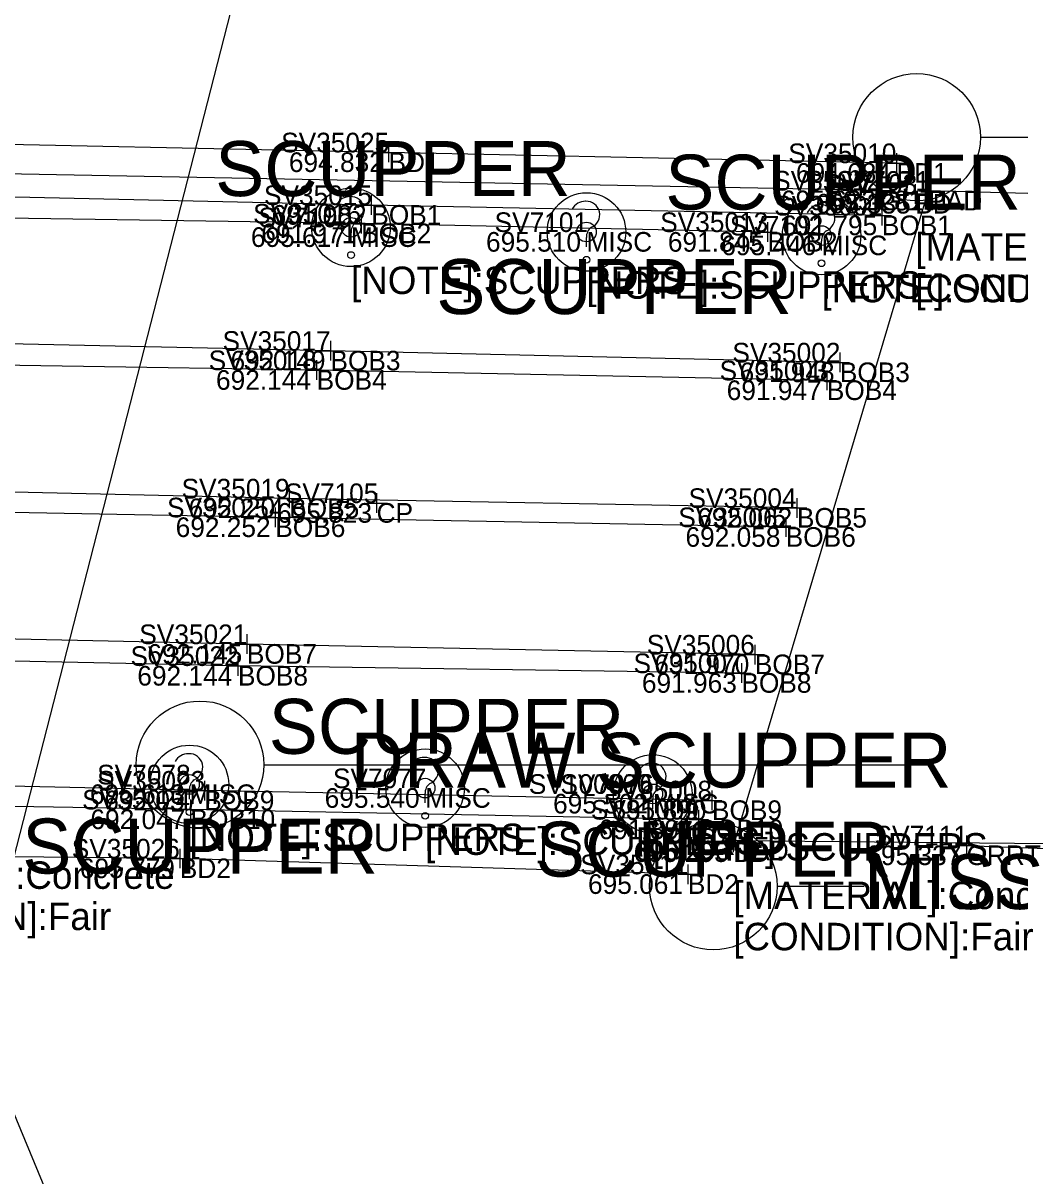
# Model space of a CAD drawing. Extents: x 1660019 to 1662995, y 619975 to 620342.
# Drawn here: x 1661479.7 to 1661530.4, y 620194.9 to 620253.7 of the extents above; entities that cross this region are included whole.
import ezdxf

# ---------------------------------------------------------------- set-up
doc = ezdxf.new("R2010")
doc.units = 0
for name, color, linetype in [('BR_X_Rail_Object', 7, 'Continuous'), ('BR_X_SV_Bottom_of_Beam', 7, 'Continuous'), ('BR_X_SV_Bottom_of_Beam_Text', 7, 'Continuous'), ('BR_X_SV_Deck_Top', 7, 'Continuous'), ('BR_X_SV_Deck_Top_Text', 7, 'Continuous'), ('PV_X_Curb', 7, 'Continuous'), ('RD_P_GR_Lt', 7, 'Continuous'), ('RD_X_Concrete_Pad', 7, 'Continuous'), ('RD_X_GR_Bar', 7, 'Continuous'), ('RD_X_GR_Rt', 7, 'Continuous'), ('RD_X_Misc_Items', 7, 'Continuous'), ('RD_X_Text', 7, 'Continuous'), ('RD_X_Wall', 7, 'Continuous'), ('SC_Scratch6', 7, 'Continuous'), ('SV_X_Text', 7, 'Continuous'), ('SV_X_Toe_of_Slope', 7, 'Continuous')]:
    doc.layers.add(name, color=color, linetype=linetype)

msp = doc.modelspace()

# ---------------------------------------------------------------- linework, layer by layer
at = {"layer": 'BR_X_SV_Bottom_of_Beam'}
for points in [[(1661523.404, 620243.849), (1661497.415, 620244.383), (1661471.694, 620244.95), (1661445.773, 620245.45), (1661419.903, 620245.974), (1661394.009, 620246.51), (1661368.147, 620247.032), (1661342.287, 620247.488), (1661316.311, 620248.045), (1661290.557, 620248.602), (1661264.648, 620249.031), (1661238.6, 620249.579)], [(1661517.582, 620243.008), (1661496.897, 620243.44), (1661470.919, 620243.838), (1661445.09, 620244.441), (1661419.147, 620244.946), (1661393.26, 620245.417), (1661367.358, 620245.921), (1661341.629, 620246.518), (1661315.646, 620247.115), (1661289.746, 620247.518), (1661264.383, 620248.322), (1661238.204, 620248.614)], [(1661521.265, 620236.365), (1661495.332, 620236.959), (1661469.491, 620237.512), (1661443.572, 620237.996), (1661417.708, 620238.508), (1661391.884, 620239.08), (1661365.994, 620239.561), (1661340.119, 620240.034), (1661314.197, 620240.589), (1661288.354, 620241.145), (1661262.476, 620241.611), (1661236.623, 620242.15)], [(1661520.605, 620235.452), (1661494.63, 620235.975), (1661468.71, 620236.383), (1661442.944, 620236.996), (1661417.103, 620237.514), (1661391.103, 620237.982), (1661365.202, 620238.448), (1661339.374, 620239.07), (1661313.502, 620239.591), (1661287.59, 620239.99), (1661261.723, 620240.632), (1661235.908, 620241.144)], [(1661519.081, 620228.953), (1661493.234, 620229.438), (1661467.368, 620230.031), (1661441.422, 620230.57), (1661415.6, 620231.071), (1661389.731, 620231.651), (1661363.823, 620232.132), (1661337.817, 620232.613), (1661311.988, 620233.076), (1661286.183, 620233.721), (1661260.328, 620234.129), (1661234.382, 620234.656)], [(1661518.51, 620227.977), (1661492.527, 620228.475), (1661466.56, 620228.954), (1661440.742, 620229.56), (1661414.823, 620230.069), (1661388.938, 620230.522), (1661363.07, 620231.021), (1661337.298, 620231.612), (1661311.527, 620232.162), (1661285.446, 620232.587), (1661259.588, 620233.138), (1661233.669, 620233.674)], [(1661516.938, 620221.488), (1661491.079, 620222.019), (1661465.187, 620222.58), (1661439.251, 620223.092), (1661413.441, 620223.61), (1661387.584, 620224.174), (1661361.703, 620224.657), (1661335.742, 620225.126), (1661309.876, 620225.693), (1661284.015, 620226.238), (1661258.155, 620226.696), (1661232.1, 620227.235)], [(1661516.255, 620220.542), (1661490.624, 620220.907), (1661464.53, 620221.454), (1661438.64, 620222.101), (1661412.707, 620222.613), (1661386.76, 620223.066), (1661360.949, 620223.557), (1661335.05, 620224.176), (1661309.206, 620224.717), (1661283.267, 620225.126), (1661257.537, 620225.694), (1661231.605, 620226.262)], [(1661514.756, 620214.059), (1661488.914, 620214.555), (1661463.017, 620215.148), (1661437.126, 620215.616), (1661411.256, 620216.167), (1661385.428, 620216.691), (1661359.541, 620217.184), (1661333.602, 620217.682), (1661307.754, 620218.183), (1661281.891, 620218.773), (1661255.858, 620219.275), (1661229.67, 620219.799)], [(1661514.073, 620213.08), (1661488.21, 620213.597), (1661462.263, 620214.044), (1661436.515, 620214.643), (1661410.516, 620215.165), (1661384.602, 620215.601), (1661358.815, 620216.084), (1661332.968, 620216.701), (1661307.113, 620217.251), (1661281.101, 620217.691), (1661255.319, 620218.266), (1661229.464, 620218.851)]]:
    msp.add_lwpolyline(points, dxfattribs=at)
at = {"layer": 'BR_X_SV_Deck_Top'}
for points in [[(1661524.154, 620246.519), (1661498.291, 620247.067), (1661472.426, 620247.598), (1661446.524, 620248.074), (1661420.55, 620248.604), (1661394.772, 620249.021), (1661368.927, 620249.743), (1661342.743, 620250.117), (1661316.866, 620250.706), (1661291.246, 620251.013), (1661265.132, 620251.796)], [(1661513.529, 620210.295), (1661487.664, 620211.099), (1661461.66, 620211.354), (1661435.632, 620211.885), (1661409.962, 620212.424), (1661383.838, 620212.928), (1661332.298, 620213.947), (1661306.248, 620214.439), (1661280.429, 620214.969), (1661254.732, 620215.771)]]:
    msp.add_lwpolyline(points, dxfattribs=at)
at = {"layer": 'PV_X_Curb'}
msp.add_lwpolyline([(1661523.342, 620245.121), (1661471.566, 620246.113), (1661445.996, 620246.597), (1661316.22, 620249.01), (1661290.79, 620249.439), (1661264.952, 620250.247), (1661238.714, 620250.79)], dxfattribs=at)
at = {"layer": 'RD_P_GR_Lt'}
for p, q in [((1661498.291, 620247.567), (1661498.291, 620246.567)), ((1661497.791, 620247.067), (1661498.791, 620247.067)), ((1661498.291, 620247.067), (1661498.291, 620247.067)), ((1661524.154, 620247.019), (1661524.154, 620246.019)), ((1661523.654, 620246.519), (1661524.654, 620246.519)), ((1661524.154, 620246.519), (1661524.154, 620246.519)), ((1661523.342, 620245.621), (1661523.342, 620244.621)), ((1661525.109, 620245.45), (1661525.109, 620244.45)), ((1661525.769, 620245.611), (1661525.769, 620244.611)), ((1661497.415, 620244.883), (1661497.415, 620243.883)), ((1661522.842, 620245.121), (1661523.842, 620245.121)), ((1661523.342, 620245.121), (1661523.342, 620245.121)), ((1661524.609, 620244.95), (1661525.609, 620244.95)), ((1661525.109, 620244.95), (1661525.109, 620244.95)), ((1661525.269, 620245.111), (1661526.269, 620245.111)), ((1661525.769, 620245.111), (1661525.769, 620245.111)), ((1661496.915, 620244.383), (1661497.915, 620244.383)), ((1661497.415, 620244.383), (1661497.415, 620244.383)), ((1661523.404, 620244.349), (1661523.404, 620243.349)), ((1661496.897, 620243.94), (1661496.897, 620242.94)), ((1661522.904, 620243.849), (1661523.904, 620243.849)), ((1661523.404, 620243.849), (1661523.404, 620243.849)), ((1661496.397, 620243.44), (1661497.397, 620243.44)), ((1661496.897, 620243.44), (1661496.897, 620243.44)), ((1661517.582, 620243.508), (1661517.582, 620242.508)), ((1661517.082, 620243.008), (1661518.082, 620243.008)), ((1661517.582, 620243.008), (1661517.582, 620243.008)), ((1661495.332, 620237.459), (1661495.332, 620236.459)), ((1661494.832, 620236.959), (1661495.832, 620236.959)), ((1661495.332, 620236.959), (1661495.332, 620236.959)), ((1661521.265, 620236.865), (1661521.265, 620235.865)), ((1661494.63, 620236.475), (1661494.63, 620235.475)), ((1661520.765, 620236.365), (1661521.765, 620236.365)), ((1661521.265, 620236.365), (1661521.265, 620236.365)), ((1661494.13, 620235.975), (1661495.13, 620235.975)), ((1661494.63, 620235.975), (1661494.63, 620235.975)), ((1661520.105, 620235.452), (1661521.105, 620235.452)), ((1661520.605, 620235.952), (1661520.605, 620234.952)), ((1661520.605, 620235.452), (1661520.605, 620235.452)), ((1661493.234, 620229.938), (1661493.234, 620228.938)), ((1661497.682, 620229.703), (1661497.682, 620228.703)), ((1661492.527, 620228.975), (1661492.527, 620227.975)), ((1661492.734, 620229.438), (1661493.734, 620229.438)), ((1661493.234, 620229.438), (1661493.234, 620229.438)), ((1661497.182, 620229.203), (1661498.182, 620229.203)), ((1661497.682, 620229.203), (1661497.682, 620229.203)), ((1661519.081, 620229.453), (1661519.081, 620228.453)), ((1661492.027, 620228.475), (1661493.027, 620228.475)), ((1661492.527, 620228.475), (1661492.527, 620228.475)), ((1661518.51, 620228.477), (1661518.51, 620227.477)), ((1661518.581, 620228.953), (1661519.581, 620228.953)), ((1661519.081, 620228.953), (1661519.081, 620228.953)), ((1661518.01, 620227.977), (1661519.01, 620227.977)), ((1661518.51, 620227.977), (1661518.51, 620227.977)), ((1661491.079, 620222.519), (1661491.079, 620221.519)), ((1661490.579, 620222.019), (1661491.579, 620222.019)), ((1661491.079, 620222.019), (1661491.079, 620222.019)), ((1661516.938, 620221.988), (1661516.938, 620220.988)), ((1661490.624, 620221.407), (1661490.624, 620220.407)), ((1661516.438, 620221.488), (1661517.438, 620221.488)), ((1661516.938, 620221.488), (1661516.938, 620221.488)), ((1661490.124, 620220.907), (1661491.124, 620220.907)), ((1661490.624, 620220.907), (1661490.624, 620220.907)), ((1661516.255, 620221.042), (1661516.255, 620220.042)), ((1661515.755, 620220.542), (1661516.755, 620220.542)), ((1661516.255, 620220.542), (1661516.255, 620220.542)), ((1661488.914, 620215.055), (1661488.914, 620214.055)), ((1661488.414, 620214.555), (1661489.414, 620214.555)), ((1661488.914, 620214.555), (1661488.914, 620214.555)), ((1661514.756, 620214.559), (1661514.756, 620213.559)), ((1661488.21, 620214.097), (1661488.21, 620213.097)), ((1661514.256, 620214.059), (1661515.256, 620214.059)), ((1661514.756, 620214.059), (1661514.756, 620214.059)), ((1661487.71, 620213.597), (1661488.71, 620213.597)), ((1661488.21, 620213.597), (1661488.21, 620213.597)), ((1661514.073, 620213.58), (1661514.073, 620212.58)), ((1661513.573, 620213.08), (1661514.573, 620213.08)), ((1661514.073, 620213.08), (1661514.073, 620213.08)), ((1661515.418, 620212.007), (1661516.418, 620212.007)), ((1661515.842, 620212.422), (1661515.842, 620211.422)), ((1661515.918, 620212.507), (1661515.918, 620211.507)), ((1661515.918, 620212.007), (1661515.918, 620212.007)), ((1661527.713, 620212.263), (1661527.713, 620211.263)), ((1661487.664, 620211.599), (1661487.664, 620210.599)), ((1661515.342, 620211.922), (1661516.342, 620211.922)), ((1661515.842, 620211.922), (1661515.842, 620211.922)), ((1661527.213, 620211.763), (1661528.213, 620211.763)), ((1661527.713, 620211.763), (1661527.713, 620211.763)), ((1661487.164, 620211.099), (1661488.164, 620211.099)), ((1661487.664, 620211.099), (1661487.664, 620211.099)), ((1661513.529, 620210.795), (1661513.529, 620209.795)), ((1661513.029, 620210.295), (1661514.029, 620210.295)), ((1661513.529, 620210.295), (1661513.529, 620210.295))]:
    msp.add_line(p, q, dxfattribs=at)
at = {"layer": 'RD_X_Concrete_Pad'}
msp.add_lwpolyline([(1661551.786, 620244.408), (1661525.769, 620245.111), (1661515.918, 620212.007), (1661542.622, 620211.759)], close=True, dxfattribs=at)
at = {"layer": 'RD_X_GR_Rt'}
msp.add_lwpolyline([(1661527.713, 620211.763), (1661596.627, 620209.068), (1661652.773, 620205.714), (1661709.087, 620204.454), (1661758.9, 620203.473), (1661840.536, 620201.815), (1661896.268, 620200.971), (1661955.332, 620199.483), (1662008.565, 620198.59), (1662063.032, 620197.376), (1662114.916, 620196.417)], dxfattribs=at)
at = {"layer": 'RD_X_Misc_Items'}
for p, q in [((1661496.381, 620242.495), (1661496.381, 620242.97)), ((1661508.369, 620242.255), (1661508.369, 620242.73)), ((1661520.336, 620242.075), (1661520.336, 620242.55)), ((1661488.157, 620214.118), (1661488.157, 620214.593)), ((1661500.155, 620213.927), (1661500.155, 620214.402)), ((1661511.742, 620213.636), (1661511.742, 620214.111)), ((1661511.742, 620213.636), (1661511.742, 620214.111))]:
    msp.add_line(p, q, dxfattribs=at)
for centre, radius in [((1661496.381, 620243.25), 2), ((1661508.369, 620243.01), 2), ((1661520.336, 620242.83), 2), ((1661496.381, 620243.25), 0.5), ((1661508.369, 620243.01), 0.5), ((1661520.336, 620242.83), 0.5), ((1661496.381, 620241.838), 0.17), ((1661508.369, 620241.598), 0.17), ((1661520.336, 620241.418), 0.17), ((1661488.157, 620214.873), 2), ((1661500.155, 620214.682), 2), ((1661511.742, 620214.391), 2), ((1661511.742, 620214.391), 2), ((1661488.157, 620214.873), 0.5), ((1661500.155, 620214.682), 0.5), ((1661511.742, 620214.391), 0.5), ((1661488.157, 620213.461), 0.17), ((1661500.155, 620213.27), 0.17), ((1661511.742, 620212.979), 0.17), ((1661511.742, 620212.979), 0.17)]:
    msp.add_circle(centre, radius, dxfattribs=at)
for centre, radius, start, end in [((1661496.317, 620244.061), 0.754, 88.32401, 152.53853), ((1661496.369, 620244.128), 0.688, 291.93294, 92.45835), ((1661508.305, 620243.821), 0.754, 88.32401, 152.53853), ((1661508.357, 620243.888), 0.688, 291.93294, 92.45835), ((1661520.272, 620243.641), 0.754, 88.32401, 152.53853), ((1661520.324, 620243.708), 0.688, 291.93294, 92.45835), ((1661496.967, 620243.012), 0.587, 125.46179, 184.08291), ((1661508.955, 620242.772), 0.587, 125.46179, 184.08291), ((1661520.922, 620242.592), 0.587, 125.46179, 184.08291), ((1661488.093, 620215.684), 0.754, 88.32401, 152.53853), ((1661488.145, 620215.751), 0.688, 291.93294, 92.45835), ((1661500.091, 620215.493), 0.754, 88.32401, 152.53853), ((1661500.143, 620215.56), 0.688, 291.93294, 92.45835), ((1661511.678, 620215.202), 0.754, 88.32401, 152.53853), ((1661511.678, 620215.202), 0.754, 88.32401, 152.53853), ((1661511.73, 620215.269), 0.688, 291.93294, 92.45835), ((1661511.73, 620215.269), 0.688, 291.93294, 92.45835), ((1661488.743, 620214.635), 0.587, 125.46179, 184.08291), ((1661500.741, 620214.444), 0.587, 125.46179, 184.08291), ((1661512.328, 620214.153), 0.587, 125.46179, 184.08291), ((1661512.328, 620214.153), 0.587, 125.46179, 184.08291)]:
    msp.add_arc(centre, radius, start, end, dxfattribs=at)
at = {"layer": 'SC_Scratch6'}
for p, q in [((1661528.424, 620247.836), (1661532.853, 620247.836)), ((1661491.937, 620215.875), (1661525.891, 620215.875)), ((1661518.072, 620209.689), (1661522.501, 620209.689))]:
    msp.add_line(p, q, dxfattribs=at)
for centre in [(1661525.179, 620247.836), (1661488.692, 620215.875), (1661514.827, 620209.689)]:
    msp.add_circle(centre, 3.245, dxfattribs=at)
at = {"layer": 'SV_X_Toe_of_Slope'}
msp.add_lwpolyline([(1661490.605, 620170.614), (1661477.149, 620203.096), (1661498.786, 620287.484), (1661510.242, 620298.378), (1661539.687, 620302.32)], dxfattribs=at)

# ---------------------------------------------------------------- texts
at = {"layer": 'BR_X_Rail_Object'}
for s, p in [('GUT1', (1661523.342, 620244.121)), ('PAD', (1661525.769, 620244.111)), ('MISC', (1661496.381, 620242.25)), ('MISC', (1661508.369, 620242.01)), ('MISC', (1661520.336, 620241.83)), ('CP', (1661497.682, 620228.203)), ('MISC', (1661488.157, 620213.873)), ('MISC', (1661500.155, 620213.682)), ('MISC', (1661511.742, 620213.391)), ('MISC', (1661511.742, 620213.391)), ('PAD', (1661515.918, 620211.007)), ('GRRT', (1661527.713, 620210.763))]:
    msp.add_text(s, height=1, dxfattribs=at).set_placement(p)
at = {"layer": 'BR_X_SV_Bottom_of_Beam_Text'}
for s, p in [('SV35015', (1661491.948, 620244.383)), ('SV35001', (1661517.926, 620243.849)), ('SV35016', (1661491.397, 620243.44)), ('691.982', (1661492.342, 620243.383)), ('BOB1', (1661497.415, 620243.383)), ('SV35013', (1661512.122, 620243.008)), ('691.795', (1661518.334, 620242.849)), ('BOB1', (1661523.404, 620242.849)), ('691.971', (1661491.815, 620242.44)), ('BOB2', (1661496.897, 620242.44)), ('691.845', (1661512.512, 620242.008)), ('BOB2', (1661517.582, 620242.008)), ('SV35017', (1661489.84, 620236.959)), ('SV35002', (1661515.796, 620236.365)), ('SV35018', (1661489.133, 620235.975)), ('692.149', (1661490.248, 620235.959)), ('BOB3', (1661495.332, 620235.959)), ('SV35003', (1661515.145, 620235.452)), ('691.948', (1661516.165, 620235.365)), ('BOB3', (1661521.265, 620235.365)), ('692.144', (1661489.508, 620234.975)), ('BOB4', (1661494.63, 620234.975)), ('691.947', (1661515.509, 620234.452)), ('BOB4', (1661520.605, 620234.452)), ('SV35019', (1661487.754, 620229.438)), ('SV35004', (1661513.563, 620228.953)), ('SV35020', (1661487.017, 620228.475)), ('692.254', (1661488.112, 620228.438)), ('BOB5', (1661493.234, 620228.438)), ('SV35005', (1661513.043, 620227.977)), ('692.062', (1661514.008, 620227.953)), ('BOB5', (1661519.081, 620227.953)), ('692.252', (1661487.454, 620227.475)), ('BOB6', (1661492.527, 620227.475)), ('692.058', (1661513.41, 620226.977)), ('BOB6', (1661518.51, 620226.977)), ('SV35021', (1661485.601, 620222.019)), ('SV35006', (1661511.438, 620221.488)), ('SV35022', (1661485.155, 620220.907)), ('692.145', (1661486.009, 620221.019)), ('BOB7', (1661491.079, 620221.019)), ('SV35007', (1661510.763, 620220.542)), ('691.970', (1661511.824, 620220.488)), ('BOB7', (1661516.938, 620220.488)), ('692.144', (1661485.502, 620219.907)), ('BOB8', (1661490.624, 620219.907)), ('691.963', (1661511.191, 620219.542)), ('BOB8', (1661516.255, 620219.542)), ('SV35023', (1661483.454, 620214.555)), ('SV35008', (1661509.259, 620214.059)), ('SV35024', (1661482.692, 620213.597)), ('692.057', (1661483.818, 620213.555)), ('BOB9', (1661488.914, 620213.555)), ('SV35009', (1661508.593, 620213.08)), ('691.890', (1661509.642, 620213.059)), ('BOB9', (1661514.756, 620213.059)), ('692.047', (1661483.114, 620212.597)), ('BOB10', (1661488.21, 620212.597)), ('691.891', (1661508.991, 620212.08)), ('BOB10', (1661514.073, 620212.08))]:
    msp.add_text(s, height=1, dxfattribs=at).set_placement(p)
at = {"layer": 'BR_X_SV_Deck_Top_Text'}
for s, p in [('SV35025', (1661492.824, 620247.067)), ('SV35010', (1661518.644, 620246.519)), ('694.832', (1661493.218, 620246.067)), ('BD1', (1661498.291, 620246.067)), ('694.684', (1661519.032, 620245.519)), ('BD1', (1661524.154, 620245.519)), ('SV7103', (1661520.447, 620244.95)), ('695.335', (1661520.039, 620243.95)), ('BD', (1661525.109, 620243.95)), ('SV7072', (1661511.171, 620211.922)), ('SV35026', (1661482.164, 620211.099)), ('695.295', (1661510.772, 620210.922)), ('BD', (1661515.842, 620210.922)), ('695.779', (1661482.58, 620210.099)), ('BD2', (1661487.664, 620210.099)), ('SV35011', (1661508.051, 620210.295)), ('695.061', (1661508.447, 620209.295)), ('BD2', (1661513.529, 620209.295))]:
    msp.add_text(s, height=1, dxfattribs=at).set_placement(p)
at = {"layer": 'RD_X_GR_Bar'}
for s, p in [('695.622', (1661518.269, 620244.121)), ('695.281', (1661520.687, 620244.111)), ('695.617', (1661491.285, 620242.25)), ('695.510', (1661503.255, 620242.01)), ('695.446', (1661515.232, 620241.83)), ('695.823', (1661492.618, 620228.203)), ('695.613', (1661483.093, 620213.873)), ('695.540', (1661495.041, 620213.682)), ('695.502', (1661506.669, 620213.391)), ('695.502', (1661506.669, 620213.391)), ('695.293', (1661510.854, 620211.007)), ('695.337', (1661522.617, 620210.763))]:
    msp.add_text(s, height=1, dxfattribs=at).set_placement(p)
at = {"layer": 'RD_X_Text'}
for p in [(1661489.466, 620244.84), (1661512.382, 620244.15), (1661500.724, 620238.831), (1661492.192, 620216.43), (1661479.644, 620210.333), (1661505.792, 620210.177)]:
    msp.add_text('SCUPPER', height=2.8, dxfattribs=at).set_placement(p)
at = {"layer": 'RD_X_Wall'}
for s, p in [('SV35012', (1661517.873, 620245.121)), ('SV7071', (1661521.089, 620245.111)), ('SV7100', (1661491.669, 620243.25)), ('SV7101', (1661503.689, 620243.01)), ('SV7102', (1661515.665, 620242.83)), ('SV7105', (1661493.013, 620229.203)), ('SV7078', (1661483.458, 620214.873)), ('SV7077', (1661495.461, 620214.682)), ('SV100000', (1661505.434, 620214.391)), ('SV7076', (1661507.04, 620214.391)), ('SV7073', (1661511.256, 620212.007)), ('SV7111', (1661523.033, 620211.763))]:
    msp.add_text(s, height=1, dxfattribs=at).set_placement(p)
at = {"layer": 'SC_Scratch6'}
for s, p in [('DRAW SCUPPER', (1661496.367, 620214.708)), ('MISSING BREAK LINES', (1661522.501, 620208.522))]:
    msp.add_text(s, height=2.79999, dxfattribs=at).set_placement(p)
at = {"layer": 'SV_X_Text'}
for s, p in [('[MATERIAL]:Concrete', (1661525.109, 620241.55)), ('[NOTE]:SCUPPERS', (1661496.381, 620239.85)), ('[NOTE]:SCUPPERS', (1661508.369, 620239.61)), ('[NOTE]:SCUPPERS', (1661520.336, 620239.43)), ('[CONDITION]:Fair', (1661525.109, 620239.45)), ('[NOTE]:SCUPPERS', (1661488.157, 620211.473)), ('[NOTE]:SCUPPERS', (1661500.155, 620211.282)), ('[NOTE]:SCUPPERS', (1661511.742, 620210.991)), ('[NOTE]:SCUPPERS', (1661511.742, 620210.991)), ('[MATERIAL]:Concrete', (1661468.881, 620209.552)), ('[MATERIAL]:Concrete', (1661515.842, 620208.522)), ('[CONDITION]:Fair', (1661468.881, 620207.452)), ('[CONDITION]:Fair', (1661515.842, 620206.422))]:
    msp.add_text(s, height=1.4, dxfattribs=at).set_placement(p)

doc.saveas('drawing.dxf')
